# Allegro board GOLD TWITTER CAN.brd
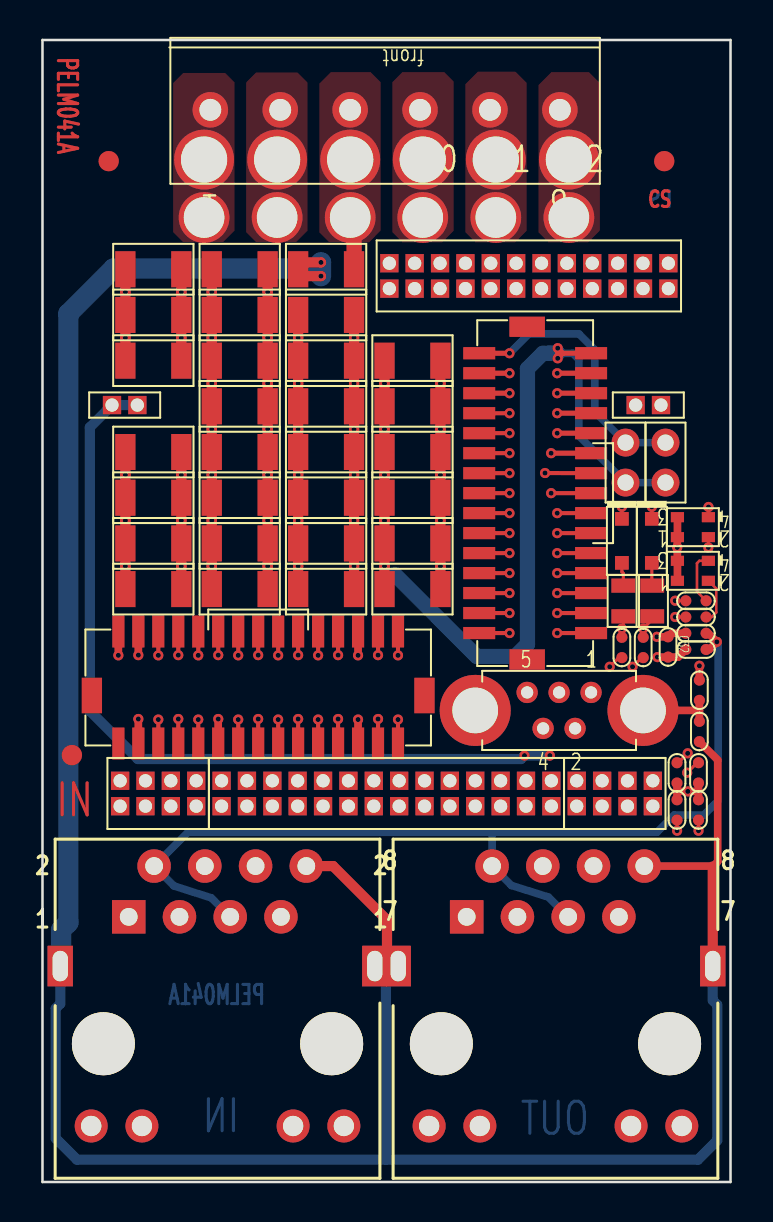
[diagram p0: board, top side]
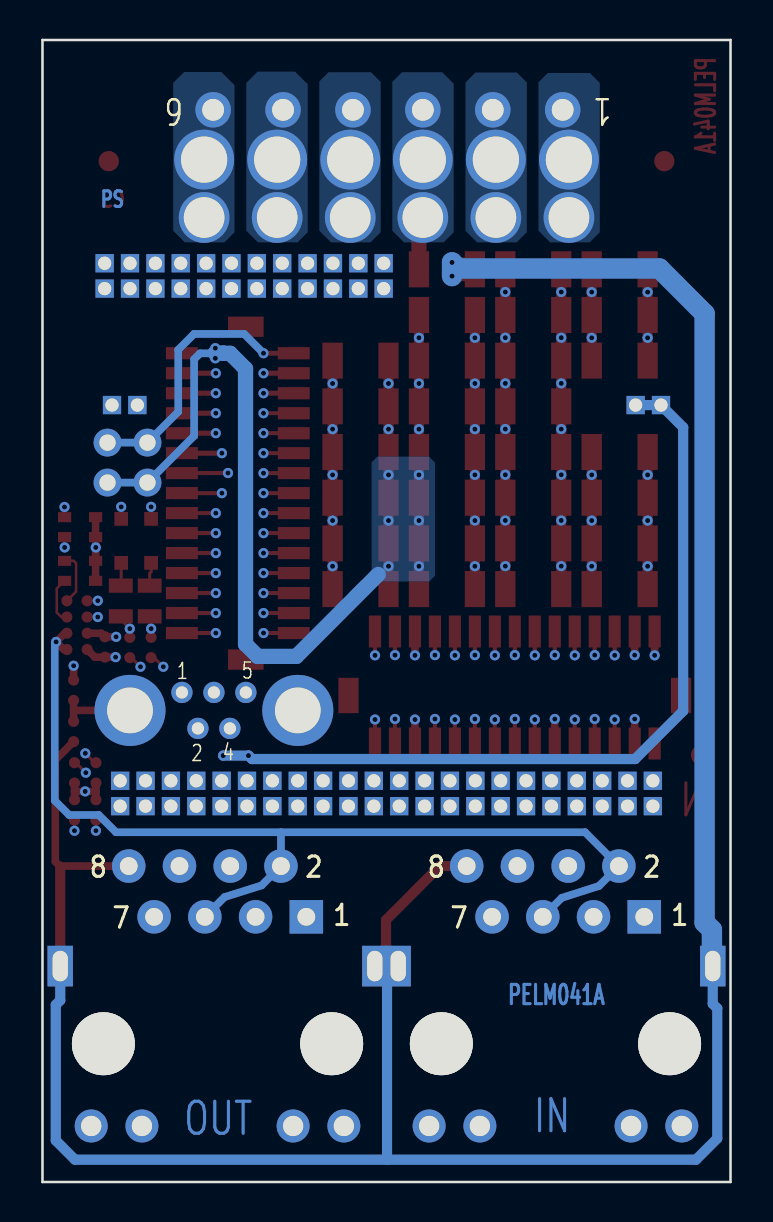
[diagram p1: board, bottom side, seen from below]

Outline 34.44 x 57.14 mm; copper layers: TOP, L2, L3, L4, L5, BOTTOM. Coordinates in mm from the lower left corner of the outline.
Outline path: 0,57.14 34.44,57.14 34.44,0 0,0 0,57.14

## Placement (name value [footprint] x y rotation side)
C1  1uF  [1206]  5.55 45.67 0 top
C2  1uF  [1206]  9.87 45.67 180 top
C4  1uF  [1206]  5.55 43.38 0 top
C5  1uF  [1206]  9.87 43.38 180 top
C6  1uF  [1206]  14.2 43.38 0 top
C7  1uF  [1206]  5.55 41.1 0 top
C8  1uF  [1206]  9.87 41.1 180 top
C9  1uF  [1206]  14.2 41.1 0 top
C10  1uF  [1206]  14.2 38.81 0 top
C11  1uF  [1206]  9.87 38.81 180 top
C12  1uF  [1206]  5.55 36.53 0 top
C13  1uF  [1206]  9.87 36.53 180 top
C14  1uF  [1206]  14.2 36.53 0 top
C15  1uF  [1206]  18.52 41.1 180 top
C16  1uF  [1206]  18.52 38.81 180 top
C17  1uF  [1206]  18.52 36.53 180 top
C18  1uF  [1206]  5.55 34.24 0 top
C19  1uF  [1206]  9.87 34.24 180 top
C20  1uF  [1206]  14.2 34.24 0 top
C21  1uF  [1206]  18.52 34.24 180 top
C22  1uF  [1206]  5.55 31.95 0 top
C23  1uF  [1206]  9.87 31.95 180 top
C24  1uF  [1206]  14.2 31.95 0 top
C25  1uF  [1206]  18.52 31.95 180 top
C26  1uF  [1206]  18.52 29.67 180 top
C27  1uF  [1206]  14.2 29.67 0 top
C28  1uF  [1206]  9.87 29.67 180 top
C29  1uF  [1206]  5.55 29.67 0 top
C32  1uF  [0402]  31.32 26.77 270 top
D1  LDR/G  [LED06]  32.56 32.77 180 top
D2  LDR/G  [LED06]  32.56 30.58 180 top
D7  DZ6.2v  [SOD323]  29.01 32.08 270 top
D8  DZ6.2v  [SOD323]  30.51 32.08 270 top
FD1  -  [FD1]  1.47 21.36 0 top
FD2  -  [FD1]  31.13 51.08 0 top
FD3  -  [FD1]  3.31 51.08 0 top
H1  H8  [H08]  8.09 48.26 0 top
H2  H8  [H08]  11.75 48.26 0 top
H3  H8  [H08]  15.41 48.26 0 top
H4  H8  [H08]  19.04 48.26 0 top
H5  H8  [H08]  22.69 48.26 0 top
H6  H8  [H08]  26.35 48.26 0 top
H7  -  [H52]  8.09 51.16 0 top
H8  -  [H52]  11.75 51.16 0 top
H9  -  [H52]  15.41 51.16 0 top
H10  -  [H52]  19.04 51.16 0 top
H11  -  [H52]  22.69 51.16 0 top
H12  -  [H52]  26.35 51.16 0 top
J1  J  [HEADER271A]  30.56 20.08 270 top
J2  J  [HEADER194]  31.33 45.97 270 top
J3  J  [HEADER245B]  25.48 20.08 270 top
J5  J  [HEADER271A]  7.7 20.08 270 top
J7  J  [HEADER52A]  31.19 37 270 top
J8  J  [HEADER278A]  29.7 38.88 0 top
J9  J  [HEADER278]  3.48 38.88 0 top
J10  J  [HEADER283]  24.67 34.47 180 top
J11  J  [HEADER283]  10.8 24.74 270 top
J12  J  [HEADER52]  29.19 37 270 top
J13  RJ45MAGNETIC  [CON37]  4.32 13.27 0 top
J14  USB  [CON40]  27.46 24.5 0 top
J15  RJ45MAGNETIC  [CON37]  21.24 13.27 0 top
J16  J  [TB54]  8.4 53.65 180 top
NOREF  -  []  -41.58 79.96 0 top
NOREF#2  -  []  0 0 0 top
NOREF#3  -  []  0 57.14 0 top
NOREF#4  -  []  0 0 0 top
NOREF#5  -  []  34.44 0 0 top
R5  0R  [0402]  32.72 27.46 180 top
R6  Demo  [0402]  32.72 26.64 0 top
R7  590R  [0402]  32.72 29.08 0 top
R8  590R  [0402]  32.72 28.27 0 top
R9  590R  [0402]  32.84 20.47 90 top
R10  590R  [0402]  32.84 18.62 270 top
R11  590R  [0402]  31.77 18.62 270 top
R12  590R  [0402]  31.77 20.47 90 top
R13  Demo  [0402]  32.89 22.54 270 top
R14  10R  [0402]  32.89 24.61 270 top
R15  0R  [1206]  14.2 45.67 180 top
R16  0R  [0402]  29.01 26.75 270 top
R17  3.74K  [0603]  29.08 29.07 90 top
R18  0R  [0402]  30.07 26.75 270 top
R19  3.74K  [0603]  30.53 29.07 90 top

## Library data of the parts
C1 C2 C4-C29 = C1uF_200v_X7R_1206
C32 = C1uF_10v_X5R_0402
D1 D2 = LED_BICOLOR_LED06
D7 D8 = MM3Z6V2_SOD323
FD1-FD3 = FIDUCIAL1_FD1
H1-H6 = HOLE08_H08
H7-H12 = HOLE52_H52
J1 J5 = HEADER2x4P1.27mm_HEADER271A
J2 = HEADER2x12PF1.27_4.3_HEADER194
J3 = HEADER2x14P1_0.27_HEADER245B
J7 = HEADER52A_FP12
J8 = HEADER2P1.27mmHEADER278A
J9 = HEADER2P1.27mm_6.5_HEADER278
J10 J11 = HEADER2x15P1mm_HEADER283
J12 = HEADER2PF2mm_4.3mm_HEADER52
J13 J15 = CON8P_RJ45MAGNET_Straight_CON37
J14 = USBType-B_TH_STR_5Pins_CON40
J16 = TB6P3.5mm_TB54
R5 R16 R18 = 0R_0402
R6 R13 = RES0402_DEMO
R7-R12 = 590R1%_0402
R14 = 10R1%_0402
R15 = 0R_1206
R17 R19 = 3.74K1%_0603

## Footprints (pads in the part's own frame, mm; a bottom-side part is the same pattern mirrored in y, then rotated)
0402
  round 0.559 smd: 1(-0.508,0) 2(0.508,0)
0603
  rect 0.711x1.194 smd: 1(-0.77,0) 2(0.77,0)
1206
  rect 1.016x1.803 smd: 1(-1.4,0) 2(1.4,0)
CON37
  round 3.15 hole 3.2 unplated: (-1.27,-6.35) (10.16,-6.35)
  rect 1.676x1.676 hole 0.889: 1(0,0)
  round 1.676 hole 0.889: 2(1.27,2.54) 3(2.54,0) 4(3.81,2.54) 5(5.08,0) 6(6.35,2.54) 7(7.62,0) 8(8.89,2.54)
  round 1.651 hole 1.016: 9(-1.88,-10.465) 10(0.66,-10.465) 11(8.23,-10.465) 12(10.77,-10.465)
  rect 1.27x2.032 hole 0.762x1.524: 13(12.319,-2.464) 14(-3.429,-2.464)
CON40
  round 1.067 hole 0.61: 1(0,0) 2(-0.8,-1.8) 3(-1.6,0) 4(-2.4,-1.8) 5(-3.2,0)
  round 3.556 hole 2.286: 6(2.6,-0.9) 7(-5.8,-0.9)
FD1
  round 1.016 smd: 1(0,0)
H08
  round 2.54 hole 2.032: 1(0,0)
H52
  round 2.997 hole 2.311: 1(0,0)
HEADER52
  round 1.397 hole 0.813: 1(0,0) 2(2,0)
HEADER52A
  round 1.397 hole 0.813: 1(0,0) 2(2,0)
HEADER194
  rect 0.914x0.914 hole 0.66: 1(0,0) 2(1.27,0) 3(0,-1.27) 4(1.27,-1.27) 5(0,-2.54) 6(1.27,-2.54) 7(0,-3.81) 8(1.27,-3.81) 9(0,-5.08) 10(1.27,-5.08) 11(0,-6.35) 12(1.27,-6.35) 13(0,-7.62) 14(1.27,-7.62) 15(0,-8.89) 16(1.27,-8.89) 17(0,-10.16) 18(1.27,-10.16) 19(0,-11.43) 20(1.27,-11.43) 21(0,-12.7) 22(1.27,-12.7) 23(0,-13.97) 24(1.27,-13.97)
HEADER245B
  rect 0.914x0.914 hole 0.66: 1(0,0) 2(1.27,0) 3(0,-1.27) 4(1.27,-1.27) 5(0,-2.54) 6(1.27,-2.54) 7(0,-3.81) 8(1.27,-3.81) 9(0,-5.08) 10(1.27,-5.08) 11(0,-6.35) 12(1.27,-6.35) 13(0,-7.62) 14(1.27,-7.62) 15(0,-8.89) 16(1.27,-8.89) 17(0,-10.16) 18(1.27,-10.16) 19(0,-11.43) 20(1.27,-11.43) 21(0,-12.7) 22(1.27,-12.7) 23(0,-13.97) 24(1.27,-13.97) 25(0,-15.24) 26(1.27,-15.24) 27(0,-16.51) 28(1.27,-16.51)
HEADER271A
  rect 0.914x0.914 hole 0.66: 1(0,0) 2(1.27,0) 3(0,-1.27) 4(1.27,-1.27) 5(0,-2.54) 6(1.27,-2.54) 7(0,-3.81) 8(1.27,-3.81)
HEADER278
  rect 0.914x0.914 hole 0.66: 1(0,0) 2(1.27,0)
HEADER278A
  rect 0.914x0.914 hole 0.66: 1(0,0) 2(1.27,0)
HEADER283
  rect 1.778x1.016 smd: (0.4,8.325) (0.4,-8.325)
  rect 1.6x0.61 smd: 1(-2.8,7) 2(2.8,7) 3(-2.8,6) 4(2.8,6) 5(-2.8,5) 6(2.8,5) 7(-2.8,4) 8(2.8,4) 9(-2.8,3) 10(2.8,3) 11(-2.8,2) 12(2.8,2) 13(-2.8,1) 14(2.8,1) 15(-2.8,0) 16(2.8,0) 17(-2.8,-1) 18(2.8,-1) 19(-2.8,-2) 20(2.8,-2) 21(-2.8,-3) 22(2.8,-3) 23(-2.8,-4) 24(2.8,-4) 25(-2.8,-5) 26(2.8,-5) 27(-2.8,-6) 28(2.8,-6) 29(-2.8,-7) 30(2.8,-7)
LED06
  rect 0.66x0.508 smd: 1(0.775,0.5) 2(-0.775,0.5) 3(0.775,-0.5) 4(-0.775,-0.5)
SOD323
  rect 0.686x0.686 smd: 1(-1.1,0) 2(1.1,0)
TB54
  round 1.778 hole 1.092: 1(0,0) 2(-3.5,0) 3(-7,0) 4(-10.5,0) 5(-14,0) 6(-17.5,0)

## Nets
3.3V: C32.1 D1.1(ANODE_R) D1.3(ANODE_G) D2.1(ANODE_R) D2.3(ANODE_G) J9.1 J9.2 R5.2 R9.1 R10.1 R11.1 R12.1
+5VE: J2.19 J10.19 J10.26
GND: C32.2 J1.3 J2.21 J2.23 J3.7 J3.8 J3.21 J3.22 J10.21 J10.23 J10.25 J10.27 J10.28 J11.5 J11.6 J11.20 J11.27 J11.28 J11.29 J14.5(GND) R6.1 R14.1
GND_POWER: J13.8(GND) J13.13(SHLD1) J13.14(SHLD2) J15.8(GND) J15.13(SHLD1) J15.14(SHLD2) R13.2 R15.2
ANALOG1+: J3.9 J11.7
ANALOG1-: J3.10 J11.8
AUX_H: J7.1 J10.30 J12.1
CANH: J3.1 R8.1
CANL: J3.2 R7.1
ENCA_A+_ABS_C+: J2.1 J10.1
ENCA_A-_ABS_C-: J2.3 J10.3
ENCA_B+_ABS_D+: J2.5 J10.5
ENCA_B-_ABS_D-: J2.7 J10.7
ENCA_INDEX+: J2.9 J10.9
ENCA_INDEX-: J2.11 J10.11
ENCB_A+: J2.4 J10.4
ENCB_A-: J2.2 J10.2
ENCB_B+: J2.8 J10.8
ENCB_B-: J2.6 J10.6
ENCB_INDEX+: J2.12 J10.12
ENCB_INDEX-: J2.10 J10.10
ENCC_A_O+: J2.16 J10.16
ENCC_A_O-: J2.14 J10.14
ENCC_B_O+: J2.20 J10.20
ENCC_B_O-: J2.18 J10.18
ENCC_INDEX_O+: J2.24 J10.24
ENCC_INDEX_O-: J2.22 J10.22
F_DC: J13.2(TDC) J13.5(RDC) J15.2(TDC) J15.5(RDC) R5.1 R6.2
GPIO5_ANALOG_IN: J3.11 J11.9
GPIO8_PAL_RS232_RX: J3.6 J11.4
GPIO9_PAL_RS232_TX: J3.5 J11.3
HA: J2.13 J10.13
HB: J2.15 J10.15
HC: J2.17 J10.17
IN1: J3.28 J11.26
IN2: J3.27 J11.25
IN3: J3.26 J11.24
IN4: J3.25 J11.23
IN5: J3.24 J11.22
IN6: J3.23 J11.21
LED1: D1.2(CATHODE_R) J3.15 J11.13
LED2: D1.4(CATHODE_G) J3.16 J11.14
M1: H4.1(H) H10.1(H) J16.4
M2: H5.1(H) H11.1(H) J16.5
M3: H6.1(H) H12.1(H) J16.6
OUT1_E: J3.20 J11.18
OUT2_E: J3.18 J11.16
OUT3_E: J3.19 J11.17
OUT4_E: J3.17 J11.15
PE: H3.1(H) H9.1(H) J16.3 R15.1
PHY1_LINK_ACT: J1.6 J15.12(LED2K)
PHY1_SPEED: J1.8 J15.10(LED1K)
PHY_IN_LINK_ACT: J1.5 J13.12(LED2K)
PHY_IN_RX+: J5.5 J13.4(RD+)
PHY_IN_RX-: J5.7 J13.6(RD-)
PHY_IN_SPEED: J1.7 J13.10(LED1K)
PHY_IN_TX+: J5.6 J13.1(TD+)
PHY_IN_TX-: J5.8 J13.3(TD-)
PHY_OUT_RX+: J5.1 J15.4(RD+)
PHY_OUT_RX-: J5.3 J15.6(RD-)
PHY_OUT_TX+: J5.2 J15.1(TD+)
PHY_OUT_TX-: J5.4 J15.3(TD-)
PR: C1.2 C2.2 C4.2 C5.2 C6.2 C7.2 C8.2 C9.2 C10.2 C11.2 C12.2 C13.2 C14.2 C15.2 C16.2 C17.2 C18.2 C19.2 C20.2 C21.2 C22.2 C23.2 C24.2 C25.2 C26.2 C27.2 C28.2 C29.2 H1.1(H) H7.1(H) J7.2 J10.29 J12.2 J16.1
RS232_RX: J3.4 J11.2
RS232_TX: J3.3 J11.1
STO1: J3.12 R16.1 R17.1
STO1_IN: D7.1(K) J11.10 R16.2
STO2: J3.14 R18.1 R19.1
STO2_IN: D8.1(K) J11.12 R18.2
STO_RET: J3.13 J11.11
USB_VBUS: J1.1 J14.1(VCC)
USBD+: J1.2 J14.3(D+)
USBD-: J1.4 J14.2(D-)
VP+: C1.1 C2.1 C4.1 C5.1 C6.1 C7.1 C8.1 C9.1 C10.1 C11.1 C12.1 C13.1 C14.1 C15.1 C16.1 C17.1 C18.1 C19.1 C20.1 C21.1 C22.1 C23.1 C24.1 C25.1 C26.1 C27.1 C28.1 C29.1 H2.1(H) H8.1(H) J16.2
N14935954: D2.4(CATHODE_G) R7.2
N14935988: D2.2(CATHODE_R) R8.2
N16763388: J13.9(LED1A) R9.2
N16763395: J13.11(LED2A) R10.2
N16763402: J15.9(LED1A) R11.2
N16763409: J15.11(LED2A) R12.2
N16765941: J14.6(SHLD1) J14.7(SHLD2) R13.1 R14.2
N16786561: D7.2(A) R17.2
N16786579: D8.2(A) R19.2

Pads without a net: FD1 1; FD2 1; FD3 1; J8 1 2; J11 19 30; J13 7; J14 4; J15 7

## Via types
v1: diameter 0.508, hole 0.254, TOP to BOTTOM, 130 vias

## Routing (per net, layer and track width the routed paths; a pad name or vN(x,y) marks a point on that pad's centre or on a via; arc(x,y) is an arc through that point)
3.3V: length 48.6
  TOP w0.381: R11.1 31.77,19.55 ; 31.77,19.55 R12.1 ; 31.77,19.55 v1(32.31,19.55) 32.84,19.55 ; D1.3 D1.1 v1(31.78,31.75) D2.3 D2.1 ; R10.1 32.84,19.55 ; 32.84,19.55 R9.1 ; v1(30.76,27.28) C32.1 31.5,27.46 R5.2
  BOTTOM w0.508: J9.2 J9.1 3.48,38.87 2.37,37.76 2.37,23.57 4.78,21.16 23.96,21.16 v1(24.13,21.34) v1(25.4,21.34)
+5VE: length 3.5
  TOP w0.254: J10.26 v1(23.38,39.47) ; J10.19 v1(25.46,36.47)
GND: length 17.8
  TOP w0.254: J10.21 v1(25.77,37.47) ; J10.25 v1(25.77,39.47) ; J10.23 v1(25.77,38.47) ; J10.27 v1(25.77,40.47) ; J10.28 v1(23.38,40.47)
  TOP w0.381: J11.5 v1(15.8,26.35) ; J11.6 v1(15.8,23.14) ; R6.1 31.83,26.26 C32.2 v1(30.78,26.26) ; J11.20 v1(8.8,23.17) ; J11.28 v1(4.8,23.17) ; J11.27 v1(4.8,26.36) ; J11.29 v1(3.8,26.35) ; R14.1 v1(32.89,25.83)
GND_POWER: length 135.9
  TOP w0.381: 33.58,15.81 33.8,16.03 33.8,21.12 R13.2 ; 33.58,15.81 J15.8 ; 33.58,15.81 33.56,15.79 ; J13.13 J15.14
  TOP w0.508: v1(13.94,46.01) 13.14,46.01 R15.2 13.14,45.33 v1(13.94,45.33) ; J13.8 14.55,15.81 17.25,13.11 17.25,10.81 ; J15.13 33.56,15.79
  BOTTOM w0.508: 17.2,1.12 32.82,1.12 33.78,2.08 33.78,8.87 33.56,9.09 J15.13 ; 17.2,1.12 17.2,10.81 ; 17.2,1.12 1.73,1.12 0.66,2.18 0.66,8.69 0.89,8.92 J13.14 ; J15.14 17.2,10.81 ; 17.2,10.81 J13.13
  BOTTOM w1.016: v1(13.94,45.33) v1(13.94,46.01) 13.64,45.71 3.56,45.71 1.3,43.45 1.3,12.98 0.93,12.62 0.93,10.85 J13.14
ANALOG1+: length 10
  TOP w0.203: J11.7 v1(14.8,26.36)
  L3 w0.178: 17.3,22.92 17.3,23.86
  L3 w0.203: 17.3,23.86 v1(14.8,26.36) ; J3.9 20.4,20.22 18.36,22.26 17.96,22.26 17.3,22.92
ANALOG1-: length 9.4
  TOP w0.203: J11.8 v1(14.8,23.17)
  L4 w0.127: 19.76,20.49 19.76,19.44
  L4 w0.203: 19.76,20.49 18.18,22.07 16.79,22.07 16.25,22.61 15.13,22.61 14.8,22.95 v1(14.8,23.17) ; 19.76,19.44 J3.10
AUX_H: length 13.8
  TOP w0.254: J10.30 v1(23.38,41.47)
  BOTTOM w0.381: v1(23.38,41.47) 24.35,42.44 26.86,42.44 27.65,41.64 27.65,38.54 J12.1 J7.1
CANH: length 15
  TOP w0.152: v1(31.68,28.27) 31.68,28.27 R8.1
  L2 w0.152: v1(31.68,28.27) 32.1,27.85 32.1,25.52 32.54,25.08 32.54,22.49 31.82,21.77 31.82,21.77 31.73,21.68 31.73,21.3 31.19,20.76 26.16,20.76 J3.1
CANL: length 19
  TOP w0.127: R7.1 v1(31.68,29.09)
  L2 w0.152: v1(31.68,29.09) 32.39,28.37 32.39,25.63 32.83,25.19 32.83,21.27 32.53,20.97 32.02,20.97 31.35,20.3 31.35,18.4 30.95,18 26.29,18 J3.2
ENCA_A+_ABS_C+: length 23.1
  TOP w0.203: J10.1 v1(25.77,27.47)
  L3 w0.127: 30.7,45.34 30.7,44.21
  L3 w0.152: J2.1 30.7,45.34 ; 30.7,44.21 30.7,44.04 30.49,43.83 29.83,43.83 28.23,42.22 28.23,29.56 26.14,27.47 v1(25.77,27.47)
ENCA_A-_ABS_C-: length 21.2
  TOP w0.203: J10.3 v1(25.77,28.47)
  L3 w0.127: 29.43,44.31 29.43,45.34
  L3 w0.152: 29.43,44.31 27.87,42.75 27.87,30.12 26.21,28.47 v1(25.77,28.47) ; 29.43,45.34 J2.3
ENCA_B+_ABS_D+: length 19.7
  TOP w0.203: J10.5 v1(25.77,29.47)
  L3 w0.127: 28.16,45.34 28.16,44.22
  L3 w0.152: 28.16,44.22 27.52,43.58 27.52,30.78 26.21,29.47 v1(25.77,29.47) ; J2.5 28.16,45.34
ENCA_B-_ABS_D-: length 18.4
  TOP w0.203: J10.7 v1(25.77,30.47)
  L3 w0.127: 26.89,44.08 26.89,45.34
  L3 w0.152: 26.89,44.08 27.17,43.8 27.17,31.38 26.25,30.47 v1(25.77,30.47) ; 26.89,45.34 J2.7
ENCA_INDEX+: length 17.6
  TOP w0.203: J10.9 v1(25.77,31.47)
  L3 w0.127: 25.62,45.34 25.62,43.26
  L3 w0.152: J2.9 25.62,45.34 ; v1(25.77,31.47) 26.18,31.47 26.81,32.1 26.81,42.07 25.62,43.26
ENCA_INDEX-: length 16.6
  TOP w0.203: J10.11 v1(25.77,32.47)
  L3 w0.127: 24.35,43.86 24.35,45.34
  L3 w0.152: v1(25.77,32.47) 26.45,33.15 26.45,41.75 24.35,43.86 ; 24.35,45.34 J2.11
ENCB_A+: length 21.9
  TOP w0.203: J10.4 v1(23.38,28.47)
  L4 w0.152: J2.4 30.06,44.45 27.69,42.07 27.69,30.4 26.27,28.98 23.89,28.98 v1(23.38,28.47)
ENCB_A-: length 23.8
  TOP w0.203: J10.2 v1(23.38,27.47)
  L4 w0.152: J2.2 31.33,44.32 30.61,43.59 29.98,43.59 28.05,41.66 28.05,29.81 26.22,27.98 23.89,27.98 v1(23.38,27.47)
ENCB_B+: length 18.8
  TOP w0.203: J10.8 v1(23.38,30.47)
  L4 w0.152: v1(23.38,30.47) 23.87,30.96 26.22,30.96 26.99,31.73 26.99,43.57 27.52,44.11 J2.8
ENCB_B-: length 20.3
  TOP w0.203: J10.6 v1(23.38,29.47)
  L4 w0.152: v1(23.38,29.47) 23.89,29.98 26.21,29.98 27.34,31.11 27.34,43.03 28.79,44.48 J2.6
ENCB_INDEX+: length 16.7
  TOP w0.203: J10.12 v1(23.38,32.47)
  L4 w0.152: v1(23.38,32.47) 23.87,32.96 25.98,32.96 26.27,33.25 26.27,33.53 26.27,41.01 26.28,41.01 26.28,41.41 26.27,41.42 26.27,41.52 26.28,41.52 26.28,41.92 26.27,41.93 26.27,42.28 24.98,43.57 J2.12
ENCB_INDEX-: length 17.6
  TOP w0.203: J10.10 v1(23.38,31.47)
  L4 w0.152: J2.10 26.25,43.94 26.63,43.56 26.63,32.47 26.13,31.97 23.88,31.97 v1(23.38,31.47)
ENCC_A_O+: length 13.4
  TOP w0.203: J10.16 v1(23.38,34.47)
  L3 w0.152: J2.16 24.89,42.25 24.89,37.26 24.89,37.26 24.53,36.91 24.53,36.1 23.92,35.49 23.92,35.01 v1(23.38,34.47)
ENCC_A_O-: length 14.2
  TOP w0.203: J10.14 v1(23.38,33.47)
  L3 w0.152: J2.14 23.71,43.9 25.26,42.36 25.26,37 24.98,36.71 24.98,36.01 24.31,35.34 24.31,34.4 v1(23.38,33.47)
ENCC_B_O+: length 12.8
  TOP w0.203: J10.20 v1(23.38,36.47)
  L3 w0.152: v1(23.38,36.47) 23.85,36.94 23.85,37.26 24.21,37.62 24.21,41.89 22.64,43.45 21.15,43.45 19.9,44.69 J2.20
ENCC_B_O-: length 13.3
  TOP w0.203: J10.18 v1(23.38,35.47)
  L3 w0.152: v1(23.38,35.47) 24.22,36.3 24.22,37.13 24.55,37.46 24.55,42.04 22.75,43.84 21.62,43.84 21.17,44.28 J2.18
ENCC_INDEX_O+: length 11.9
  TOP w0.203: J10.24 v1(23.38,38.47)
  L3 w0.152: J2.24 18.37,43.7 19.91,43.7 20.72,42.88 22.04,42.88 22.8,42.12 22.8,39.05 v1(23.38,38.47)
ENCC_INDEX_O-: length 12.4
  TOP w0.203: J10.22 v1(23.38,37.47)
  L3 w0.152: v1(23.38,37.47) 23.87,37.96 23.87,41.7 22.4,43.17 21.03,43.17 21.03,43.17 20.87,43.17 20.06,43.99 19.34,43.99 19.19,44.14 19.19,44.14 J2.22
F_DC: length 50.1
  TOP w0.381: R5.1 33.33,27.46 v1(33.76,27.03) 33.38,26.64 R6.2
  BOTTOM w0.381: J13.5 8.45,14.22 6.58,14.81 J13.2 7.28,17.5 22.51,17.5 ; 22.51,17.5 J15.2 23.48,14.84 25.33,14.26 J15.5 ; 22.51,17.5 30.76,17.5 31.63,18.37 33.11,18.37 33.83,19.08 33.83,26.96 v1(33.76,27.03)
GPIO5_ANALOG_IN: length 10
  TOP w0.203: J11.9 v1(13.8,26.35)
  L3 w0.178: 16.3,22.93 16.3,23.85
  L3 w0.203: 16.3,23.85 v1(13.8,26.35) ; J3.11 19.13,20.64 17.91,21.85 17.37,21.85 16.3,22.93
GPIO8_PAL_RS232_RX: length 9.8
  TOP w0.203: J11.4 v1(16.8,23.17)
  L4 w0.127: 22.3,19.44 22.3,20.42
  L4 w0.203: v1(16.8,23.17) 16.8,23.05 17.35,22.5 18.49,22.5 20.22,20.77 21.95,20.77 22.3,20.42 ; J3.6 22.3,19.44
GPIO9_PAL_RS232_TX: length 11.1
  TOP w0.203: J11.3 v1(16.8,26.36)
  L3 w0.203: v1(16.8,26.36) 18.36,24.8 18.36,22.95 20.3,21.01 22.19,21.01 22.94,20.27 J3.5
HA: length 16
  TOP w0.203: J10.13 v1(25.77,33.47)
  L4 w0.127: 23.08,43.78 23.08,45.34
  L4 w0.152: v1(25.77,33.47) 25.77,33.47 25.96,33.66 25.96,36.79 25.8,36.96 25.34,36.96 25.07,37.22 25.07,41.79 23.08,43.78 ; 23.08,45.34 J2.13
HB: length 15.8
  TOP w0.203: J10.15 v1(25.46,34.47)
  L4 w0.127: 21.81,44.22 21.81,45.33
  L4 w0.152: v1(25.46,34.47) 25.65,34.65 25.65,35.7 25.39,35.96 25.06,35.96 24.71,36.31 24.71,41.63 22.29,44.04 21.98,44.04 21.81,44.22 ; 21.81,45.33 J2.15
HC: length 15.7
  TOP w0.203: J10.17 v1(25.16,35.47)
  L4 w0.127: 20.54,45.33 20.54,44.37
  L4 w0.152: v1(25.16,35.47) 24.91,35.47 24.39,36 24.39,41.45 22.19,43.64 21.26,43.64 20.54,44.37 ; J2.17 20.54,45.33
IN1: length 8.3
  TOP w0.203: J11.26 v1(5.8,23.14)
  L4 w0.127: 9.6,19.44 9.6,20.88
  L4 w0.203: J3.28 8.97,18.81 9.6,19.44 ; v1(5.8,23.14) 7.81,21.13 9.35,21.13 9.6,20.88
IN2: length 8.8
  TOP w0.203: J11.25 v1(5.8,26.35)
  L3 w0.178: 8.3,22.42 8.3,23.85
  L3 w0.203: 8.3,22.42 8.97,21.75 J3.27 ; 8.3,23.85 v1(5.8,26.35)
IN3: length 8.5
  TOP w0.203: J11.24 v1(6.8,23.17)
  L4 w0.127: 10.87,19.44 10.87,20.73
  L4 w0.203: 10.87,20.73 10.41,21.19 10.09,21.19 9.89,21.39 9.89,21.4 9.66,21.63 8.34,21.63 v1(6.8,23.17) ; 10.87,19.44 10.24,18.81 J3.26
IN4: length 8.9
  TOP w0.203: J11.23 v1(6.8,26.36)
  L3 w0.178: 9.3,22.5 9.3,23.86
  L3 w0.203: J3.25 10.24,21.56 9.3,22.5 ; 9.3,23.86 v1(6.8,26.36)
IN5: length 8.6
  TOP w0.203: J11.22 v1(7.8,23.14)
  L4 w0.127: 12.13,19.43 12.13,20.55
  L4 w0.203: 12.13,19.43 11.51,18.81 J3.24 ; 12.13,20.55 11.77,20.9 11.57,20.9 11.32,20.9 10.87,21.36 10.87,21.36 9.62,22.61 8.33,22.61 v1(7.8,23.14)
IN6: length 9
  TOP w0.203: J11.21 v1(7.8,26.35)
  L3 w0.178: 10.3,22.4 10.3,23.85
  L3 w0.203: 10.3,22.4 11.51,21.19 J3.23 ; 10.3,23.85 v1(7.8,26.35)
LED1: length 35.3
  TOP w0.127: D1.2 v1(33.33,31.75)
  TOP w0.203: J11.13 v1(11.8,26.35)
  L2 w0.152: v1(33.33,31.75) 33.33,31.05 32.61,30.33 29.34,30.33 28.93,29.92 28.93,29.26 28.35,28.68 28.35,28.04 26.34,26.04 20.22,26.04 18.92,24.74 18.92,21.31 18.49,20.88 17.39,20.88 J3.15
  L3 w0.178: 14.3,22.43 14.3,23.85
  L3 w0.203: J3.15 16.59,21.16 15.87,21.87 14.86,21.87 14.3,22.43 ; 14.3,23.85 v1(11.8,26.35)
LED2: length 37.8
  TOP w0.127: D1.4 v1(33.34,33.77)
  TOP w0.203: J11.14 v1(11.8,23.14)
  L2 w0.127: 15.95,20.5 15.95,19.44
  L2 w0.152: v1(33.34,33.77) 33.34,32.58 32.84,32.08 32.84,30.98 32.47,30.61 29.21,30.61 28.65,30.05 28.65,29.39 28.07,28.8 28.07,28.17 26.21,26.31 20.09,26.31 18.64,24.87 18.64,21.46 18.34,21.16 16.61,21.16 15.95,20.5 ; 15.95,19.44 J3.16
  L4 w0.127: 15.95,20.5 15.95,19.44
  L4 w0.203: 15.95,20.5 15.16,21.29 13.94,21.29 13.16,22.07 12.87,22.07 v1(11.8,23.14) ; 15.95,19.44 J3.16
Net_10: length 1.2
  TOP w0.203: 8.8,27.54 v1(8.8,26.36)
OUT1_E: length 7.8
  TOP w0.203: J11.18 v1(9.8,23.14)
  L4 w0.127: 13.41,20.45 13.41,19.44
  L4 w0.203: v1(9.8,23.14) 10.38,22.56 10.67,22.56 12.2,21.03 12.83,21.03 13.41,20.45 ; 13.41,19.44 J3.20
OUT2_E: length 8.3
  TOP w0.203: J11.16 v1(10.8,23.17)
  L4 w0.127: 14.68,20.47 14.68,19.44
  L4 w0.203: v1(10.8,23.17) 10.8,22.97 12.28,21.49 13.18,21.49 13.79,20.88 14.27,20.88 14.68,20.47 ; 14.68,19.44 J3.18
OUT3_E: length 9.2
  TOP w0.203: J11.17 v1(9.8,26.35)
  L3 w0.178: 11.3,23.44 11.3,22.91
  L3 w0.203: 11.3,22.91 14.05,20.17 J3.19 ; v1(9.8,26.35) 11.3,24.85 11.3,23.44
OUT4_E: length 9.3
  TOP w0.203: J11.15 v1(10.8,26.36)
  L3 w0.178: 13.3,22.95 13.3,23.52
  L3 w0.203: 13.3,22.95 13.3,22.31 15.32,20.29 J3.17 ; 13.3,23.52 13.3,23.86 v1(10.8,26.36)
PE: length 2.7
  TOP w0.762: R15.1 15.6,48.07 H3.1
PHY1_LINK_ACT: length 20.1
  L4 w0.152: J1.6 28.79,18.03 30.23,18.03 32.54,15.72 32.54,9.58 33.96,8.15 33.96,4.76 J15.12
PHY1_SPEED: length 30.3
  L4 w0.152: J1.8 28.15,17.4 30.35,17.4 32.23,15.52 32.23,9.47 33.66,8.05 33.66,5.51 32.27,4.13 28.38,4.13 27.06,2.8 J15.10
PHY_IN_LINK_ACT: length 34.8
  L3 w0.127: 28.65,19.43 28.65,18.2 28.65,18.2
  L3 w0.152: J1.5 28.62,19.47 28.62,19.46 28.65,19.43 ; J13.12 16.6,1.29 26.17,1.29 28.93,4.05 28.93,7.71 31.42,10.2 31.42,16.61 31.27,16.76 31.27,16.76 30.22,17.82 29.03,17.82 28.65,18.2
PHY_IN_RX+: length 12.8
  L3 w0.127: 4.52,19.44 4.52,18.31
  L3 w0.152: 4.52,18.31 3.64,17.43 3.64,15.69 4.62,14.71 8.92,14.71 9.19,14.99 9.19,15.52 8.91,15.81 J13.4 ; J5.5 4.52,19.44
PHY_IN_RX-: length 13.8
  L3 w0.152: J5.7 3.89,20.07 3.12,19.3 3.12,18.16 3.32,17.97 3.32,15.56 4.47,14.4 9.26,14.4 9.58,14.72 9.58,15.54 9.85,15.81 J13.6
PHY_IN_SPEED: length 52.5
  L5 w0.127: 27.38,19.44 27.38,18.34
  L5 w0.152: J13.10 7.17,0.61 32.41,0.61 33.66,1.85 33.66,8.1 32.33,9.42 32.33,15.56 30.19,17.71 28.01,17.71 27.38,18.34 ; 27.38,19.44 26.75,20.08 J1.7
PHY_IN_TX+: length 5.9
  L4 w0.152: J5.6 5.16,18.62 4.5,17.96 4.5,13.45 J13.1
PHY_IN_TX-: length 11
  L4 w0.152: J13.3 5.93,13.27 4.85,12.19 3.66,12.19 3.17,12.67 3.17,13.89 4.19,14.91 4.19,17.98 3.89,18.29 J5.8
PHY_OUT_RX+: length 23.6
  L3 w0.127: 7.06,18.34 7.06,19.44
  L3 w0.152: 7.06,19.44 J5.1 ; 7.06,18.34 7.58,17.82 7.92,17.49 16.49,17.49 16.49,17.49 17.07,16.91 26.01,16.91 26.16,16.76 26.16,16.13 25.84,15.81 J15.4
PHY_OUT_RX-: length 26
  L3 w0.127: 8.33,20.43 8.33,18.5
  L3 w0.152: 8.33,20.43 8.02,20.74 7.09,20.74 J5.3 ; J15.6 26.79,15.81 26.5,16.1 26.5,16.9 26.2,17.19 17.29,17.19 16.71,17.78 8.11,17.78 7.95,17.93 7.95,18.12 8.33,18.5
PHY_OUT_TX+: length 17.2
  L4 w0.152: J15.1 20.09,13.27 16.19,17.17 7.58,17.17 7.24,17.51 7.24,18.35 J5.2
PHY_OUT_TX-: length 21.1
  L4 w0.152: J15.3 22.9,13.27 21.82,12.19 20.73,12.19 19.91,13 19.91,13 16.03,16.88 7.45,16.88 6.88,17.45 6.88,18.35 J5.4
PR: length 90.7
  TOP w0.254: 26.05,41.47 v1(25.79,41.72) v1(25.79,41.21) 26.05,41.47 ; 26.05,41.47 J10.29
  TOP w0.508: C7.2 v1(6.95,42.24) C4.2 v1(6.95,44.53) C1.2 ; C29.2 v1(6.95,30.81) C22.2 v1(6.95,33.1) C18.2 v1(6.95,35.38) C12.2 ; C26.2 v1(17.12,30.81) C25.2 v1(17.12,33.1) C21.2 v1(17.12,35.38) C17.2 v1(17.12,37.67) C16.2 v1(17.12,39.95) C15.2 ; C28.2 v1(8.47,30.82) C23.2 v1(8.47,33.1) C19.2 v1(8.47,35.39) C13.2 v1(8.47,37.67) C11.2 v1(8.47,39.96) C8.2 v1(8.47,42.25) C5.2 v1(8.47,44.53) C2.2 ; C6.2 v1(15.6,42.24) C9.2 v1(15.6,39.95) C10.2 v1(15.6,37.67) C14.2 v1(15.6,35.38) C20.2 v1(15.6,33.1) C24.2 v1(15.6,30.81) C27.2
  BOTTOM w0.381: 26.05,41.46 26.56,41.46 26.85,41.16 26.85,37.33 J12.2 J7.2 ; 26.05,41.46 v1(25.79,41.72) v1(25.79,41.21) 26.04,41.46 26.05,41.46
  BOTTOM w0.762: 25.79,41.48 25.38,41.48 25.37,41.46 25.05,41.46 24.28,40.69 24.28,26.91 23.67,26.3 21.74,26.3 17.63,30.4
RS232_RX: length 10
  TOP w0.203: J11.2 v1(17.8,23.14)
  L4 w0.127: 23.57,19.44 23.57,20.45
  L4 w0.203: 23.57,20.45 22.78,21.24 20.42,21.24 18.52,23.14 v1(17.8,23.14) ; J3.4 23.57,19.44
RS232_TX: length 11.6
  TOP w0.203: J11.1 v1(17.8,26.35)
  L3 w0.203: J3.3 24.21,20.33 23.07,21.46 20.57,21.46 18.88,23.15 18.88,25.27 v1(17.8,26.35)
STO1: length 25.1
  TOP w0.152: R17.1 29.08,27.76 v1(29.01,27.69) R16.1
  L3 w0.127: 26.11,18.33 26.11,19.53 26.11,19.54 26.11,20.61 26.11,20.62 26.11,20.7
  L3 w0.152: 26.11,20.7 26.12,20.71 26.12,20.86 26.53,21.28 30.98,21.28 32.21,22.51 32.21,25.11 31.62,25.7 31.62,26.54 31.37,26.8 29.9,26.8 v1(29.01,27.69) ; J3.12 19.13,18.8 19.8,18.13 25.9,18.13 26.11,18.33
STO1_IN: length 28.1
  TOP w0.152: v1(28.4,25.78) 28.85,26.24 R16.2 ; D7.1 v1(29.01,33.78)
  TOP w0.203: J11.10 v1(13.8,23.14)
  L3 w0.152: v1(29.01,33.78) 29.59,33.2 29.59,29.76 28.03,28.21 28.03,26.72 28.4,26.35 v1(28.4,25.78)
  L4 w0.152: v1(13.8,23.14) 13.8,24.03 14.56,24.78 19.35,24.78 20.62,26.05 28.13,26.05 v1(28.4,25.78)
STO2: length 26.9
  TOP w0.152: R18.1 v1(30.07,27.69) 30.53,28.16 R19.1
  L3 w0.127: 27.4,18.23 27.4,18.27 27.4,18.27 27.4,19.34 27.4,19.34 27.4,19.52 27.38,19.54 27.38,20.61 27.4,20.63 27.4,20.66 27.71,20.97
  L3 w0.152: J3.14 17.86,18.8 18.84,17.82 26.99,17.82 27.4,18.23 ; v1(30.07,27.69) 30.23,27.84 31.22,27.84 32.03,27.03 32.03,25.78 32.57,25.24 32.57,22.42 31.12,20.97 27.71,20.97
STO2_IN: length 30.6
  TOP w0.152: v1(29.54,25.78) 30,26.24 R18.2 ; D8.1 v1(30.51,33.78)
  TOP w0.203: J11.12 v1(12.8,23.17)
  L3 w0.152: v1(29.54,25.78) 28.35,26.98 28.35,28.12 29.88,29.66 29.88,33.16 v1(30.51,33.78)
  L4 w0.152: v1(29.54,25.78) 28.97,26.35 20.49,26.35 19.21,25.06 14.13,25.06 12.8,23.73 v1(12.8,23.17)
STO_RET: length 9.9
  TOP w0.203: J11.11 v1(12.8,26.36)
  L3 w0.178: 15.3,23.87 15.3,22.64
  L3 w0.203: J3.13 17.86,20.68 16.17,22.36 15.57,22.36 15.3,22.64 ; v1(12.8,26.36) 15.3,23.87
USB_VBUS: length 6.1
  L4 w0.152: J14.1 27.46,23.62 27.92,23.16 27.92,22.55 29.24,21.23 29.98,21.23 30.56,20.65 J1.1
USBD+: length 8
  L4 w0.127: 29.92,20.5 29.92,19.44
  L4 w0.152: J14.3 26.75,23.61 26.95,23.61 27.58,22.99 27.58,22.34 29.09,20.83 29.59,20.83 29.92,20.5 ; 29.92,19.44 J1.2
USBD-: length 5
  L4 w0.127: 28.65,19.44 28.65,20.71
  L4 w0.152: J1.4 28.65,19.44 ; 28.65,20.71 J14.2
VP+: length 52.6
  TOP w0.508: C7.1 v1(4.15,42.24) C4.1 v1(4.15,44.53) C1.1 ; C29.1 v1(4.15,30.81) C22.1 v1(4.15,33.1) C18.1 v1(4.15,35.38) C12.1 ; C6.1 v1(12.8,42.24) C9.1 v1(12.8,39.95) C10.1 v1(12.8,37.67) C14.1 v1(12.8,35.38) C20.1 v1(12.8,33.1) C24.1 v1(12.8,30.81) C27.1 ; C15.1 v1(19.92,39.95) C16.1 v1(19.92,37.67) C17.1 v1(19.92,35.38) C21.1 v1(19.92,33.1) C25.1 v1(19.92,30.81) C26.1 ; C2.1 v1(11.27,44.53) C5.1 v1(11.27,42.25) C8.1 v1(11.27,39.96) C11.1 v1(11.27,37.67) C13.1 v1(11.27,35.39) C19.1 v1(11.27,33.1) C23.1 v1(11.27,30.82) C28.1
N14935954: length 2.7
  TOP w0.127: R7.2 32.77,29.54 32.77,30.96 32.89,31.08 D2.4
N14935988: length 2.4
  TOP w0.127: R8.2 33.5,28.27 33.73,28.5 33.73,29.69 33.34,30.08 D2.2
N16763388: length 53.3
  TOP w0.152: v1(32.28,20.48) 32.77,20.98 R9.2
  L3 w0.152: v1(32.28,20.48) 33.38,19.38 33.38,14.3 32.41,13.34 32.41,9.5 33.96,7.95 33.96,2.44 32.37,0.85 4.39,0.85 J13.9
N16763395: length 39.5
  TOP w0.152: R10.2 v1(32.84,17.58)
  L2 w0.152: v1(32.84,17.58) 32.23,16.97 32.23,9.86 33.95,8.14 33.95,2.1 32.92,1.07 14.28,1.07 J13.11
N16763402: length 31.6
  TOP w0.152: R11.2 v1(31.77,17.58)
  L2 w0.152: v1(31.77,17.58) 31.77,9.86 33.65,7.98 33.65,2.51 32.65,1.51 20.65,1.51 J15.9
N16763409: length 25.9
  TOP w0.152: v1(32.3,21.45) 31.83,20.98 R12.2
  L3 w0.152: J15.11 30.53,1.74 32.53,1.74 33.66,2.88 33.66,7.81 31.9,9.58 31.9,15.54 32.31,15.95 32.31,18.42 31.64,19.09 31.64,20.79 v1(32.3,21.45)
N16765941: length 13.9
  TOP w0.381: 32.89,23.6 R13.1 ; 32.89,23.6 R14.2 ; 32.89,23.6 J14.6
  L3 w0.381: J14.6 29.67,23.6 27.69,25.58 23.64,25.58 J14.7
N16786561: length 1.2
  TOP w0.152: D7.2 29.01,30.53 29.08,30.46 R17.2
N16786579: length 1.1
  TOP w0.152: D8.2 30.51,29.86 R19.2

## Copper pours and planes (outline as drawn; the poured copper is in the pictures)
3.3V on L2: 31.84,18.09 31.49,18.44 31.49,19.73 32.37,20.61 32.37,21.09 31.28,21.09 31,20.81 19.52,20.81 19.28,21.06 19.28,22.69 19.27,22.7 19.27,24.44 20.49,25.66 25.88,25.66 26.59,26.38 26.59,26.37 27.02,26.37 28.19,27.54 28.19,28.09 29.16,29.06 29.16,30.74 29.59,30.74 29.16,31.17 29.16,33.68 29.57,34.09 31.6,34.09 32.38,34.87 33.53,34.87 33.93,34.47 33.93,18.87 33.15,18.09
+5VE on L2: 28.47,34.47 28.47,29.01 26.22,26.75 21.47,26.75 21.15,27.07 21.15,41.68 20.01,42.81 17.08,42.81 16.6,43.29 16.6,46.25 16.97,46.62 33.08,46.62 33.96,45.75 33.96,35.69 33.53,35.26 29.36,35.26 28.47,35.26 ; 1 cut-out
GND on L2: 19.96,27.53 3.33,27.53 2.64,26.85 2.64,15.24 3.73,14.15 30.73,14.15 31.24,14.66 31.24,16.81 30.4,17.65 26.01,17.65 25.48,18.19 25.49,18.2 25.49,20.33 25.1,20.72 19.17,20.72 18.31,21.58 18.31,25.07 19.61,26.37 19.63,26.37 20.17,26.9 20.17,27.33
GND on L5: 21.14,28.2 21.15,41.05 21.15,41.66 20.04,42.81 17.08,42.81 16.6,43.29 16.6,46.17 16.97,46.54 16.97,46.61 33.09,46.61 33.96,45.75 33.96,16.28 31.82,14.14 3.76,14.14 2.64,15.26 2.64,26.87 3.33,27.56 20.16,27.56 20.51,27.56 ; 2 cut-outs
M1 on TOP, BOTTOM, L2, L3, L4, L5: 17.51,47.52 17.51,55.03 18.01,55.53 20.12,55.53 20.59,55.06 20.59,47.6 20,47.02 18.02,47.02
M2 on TOP, BOTTOM, L2, L3, L4, L5: 21.17,47.52 21.17,54.93 21.8,55.56 23.67,55.56 24.24,54.98 24.24,47.6 23.66,47.02 21.68,47.02
M3 on TOP, BOTTOM, L2, L3, L4, L5: 24.83,47.52 24.83,54.89 25.48,55.54 27.35,55.54 27.9,54.99 27.9,47.6 27.32,47.02 25.34,47.02
PE on TOP, BOTTOM, L2, L3, L4, L5: 13.86,47.52 13.86,54.96 14.43,55.53 16.43,55.53 16.93,55.04 16.93,47.6 16.34,47.02 14.36,47.02
PR on TOP, BOTTOM, L3, L5: 6.54,47.52 6.54,54.99 7.04,55.49 9.15,55.49 9.61,55.02 9.61,47.6 9.03,47.02 7.05,47.02
PR on BOTTOM: 15.09,36.3 17.68,36.3 17.97,36 17.97,30.05 15.08,30.05 14.8,30.33 14.8,36.01
PR on L2: 3.69,28.76 3.52,28.93 3.52,37.8 3.8,38.07 5.96,38.07 6.21,38.33 6.21,39.5 5.98,39.73 3.75,39.73 3.52,39.95 3.52,46.79 3.64,46.92 5.83,46.92 6.54,47.63 6.54,54.99 7.04,55.49 9.15,55.49 9.61,55.02 9.61,47.62 10.55,46.69 11.72,46.69 11.91,46.49 11.91,44.84 12.31,44.45 15.94,44.45 16.22,44.17 16.22,42.82 16.65,42.39 19.96,42.39 20.51,41.84 20.51,40.18 19.29,39.95 20.51,39.73 20.51,37.89 19.29,37.67 20.51,37.44 20.51,35.61 19.29,35.38 20.51,35.16 20.51,33.32 19.29,33.1 20.51,32.87 20.51,31.04 19.29,30.81 20.51,30.58 20.51,28.84 20.43,28.76 ; 18 cut-outs
PR on L4: 3.69,28.76 3.52,28.93 3.52,37.8 3.8,38.07 5.96,38.07 6.21,38.33 6.21,39.5 5.98,39.73 3.75,39.73 3.52,39.95 3.52,46.79 3.64,46.92 5.83,46.92 6.54,47.63 6.54,54.99 7.04,55.49 9.15,55.49 9.61,55.02 9.61,47.62 10.55,46.69 11.72,46.69 11.91,46.49 11.91,44.84 12.31,44.45 15.94,44.45 16.22,44.17 16.22,42.82 16.65,42.39 19.96,42.39 20.51,41.84 20.51,40.18 19.29,39.95 20.51,39.73 20.51,37.89 19.29,37.67 20.51,37.44 20.51,35.61 19.29,35.38 20.51,35.16 20.51,33.32 19.29,33.1 20.51,32.87 20.51,31.04 19.29,30.81 20.51,30.58 20.51,28.84 20.43,28.76 ; 18 cut-outs
VP+ on TOP, BOTTOM, L2, L4: 10.2,47.52 10.2,55.03 10.68,55.51 12.77,55.51 13.27,55.01 13.27,47.6 12.69,47.02 10.71,47.02
VP+ on L3: 20.43,28.76 3.69,28.76 3.52,28.93 3.52,37.8 3.8,38.07 5.96,38.07 6.21,38.33 6.21,39.5 5.98,39.73 3.75,39.73 3.52,39.95 3.52,46.79 3.66,46.93 6.62,46.93 6.88,46.66 9.19,46.66 10.2,47.66 10.2,55.03 10.68,55.51 12.77,55.51 13.27,55.01 13.27,45.11 13.93,44.45 15.94,44.45 16.22,44.17 16.22,42.82 16.65,42.39 19.96,42.39 20.51,41.84 20.51,28.84 ; 23 cut-outs
VP+ on L5: 3.69,28.76 3.52,28.93 3.52,37.8 3.8,38.07 5.96,38.07 6.21,38.33 6.21,39.5 5.98,39.73 3.75,39.73 3.52,39.95 3.52,46.79 3.66,46.93 6.62,46.93 6.88,46.66 9.19,46.66 10.2,47.66 10.2,55.03 10.68,55.51 12.77,55.51 13.27,55.01 13.27,45.11 13.93,44.45 15.94,44.45 16.21,44.18 16.21,42.83 16.65,42.39 19.96,42.39 20.51,41.84 20.51,28.84 20.43,28.76 ; 23 cut-outs

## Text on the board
BOTTOM: PS | PELM041A | IN | OUT | LAYER NO.6 BOTTOM
Ref Des/Assembly Bottom: ASSEMBLY P.S.
Board Geometry/Soldermask Bottom: SOLDERMASK P.S.
Package Geometry/Pastemask Bottom: PASTEMASK P.S.
Ref Des/Silkscreen Bottom: SILKSCREEN P.S.
TOP: CS | PELM041A | IN | LAYER NO.1 TOP
Ref Des/Assembly Top: C32 | ASSEMBLY C.S.
Board Geometry/Soldermask Top: SOLDERMASK C.S.
Package Geometry/Pastemask Top: PASTEMASK C.S.
Ref Des/Silkscreen Top: SILKSCREEN C.S.
L2: LAYER NO.2 L2
L3: LAYER NO.3 L3
L4: LAYER NO.4 L4
L5: LAYER NO.5 L5
User.7: FIGURE | SIZE | 10.0 | 24.0 | 26.0 | 32.0 | 35.0 | 40.0 | 43.0 | 80.0 | 90.0 | 91.0 | 126.0 | 60.0x30.0 | DRILL CHART: TOP to BOTTOM | ALL UNITS ARE IN MILS | TOLERANCE | +4.0/-2.0 | +2.0/-2.0 | PLATED | NON-PLATED | QTY | 130 | 5 | 72 | 4 | 16 | 8 | 6 | 2
User.10: 47.1 | 30 | 1.60
User.14: DRILL
